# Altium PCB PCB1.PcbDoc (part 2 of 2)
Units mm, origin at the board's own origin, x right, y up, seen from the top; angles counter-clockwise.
Board outline 100 x 100 mm, 4 copper layers (Top Layer, Layer 1, Layer 2, Bottom Layer), stack 1.578 mm thick; 186 components, 85 nets, 396 pads, 143 vias.
Unrouted connection lines stored in the file: 19.
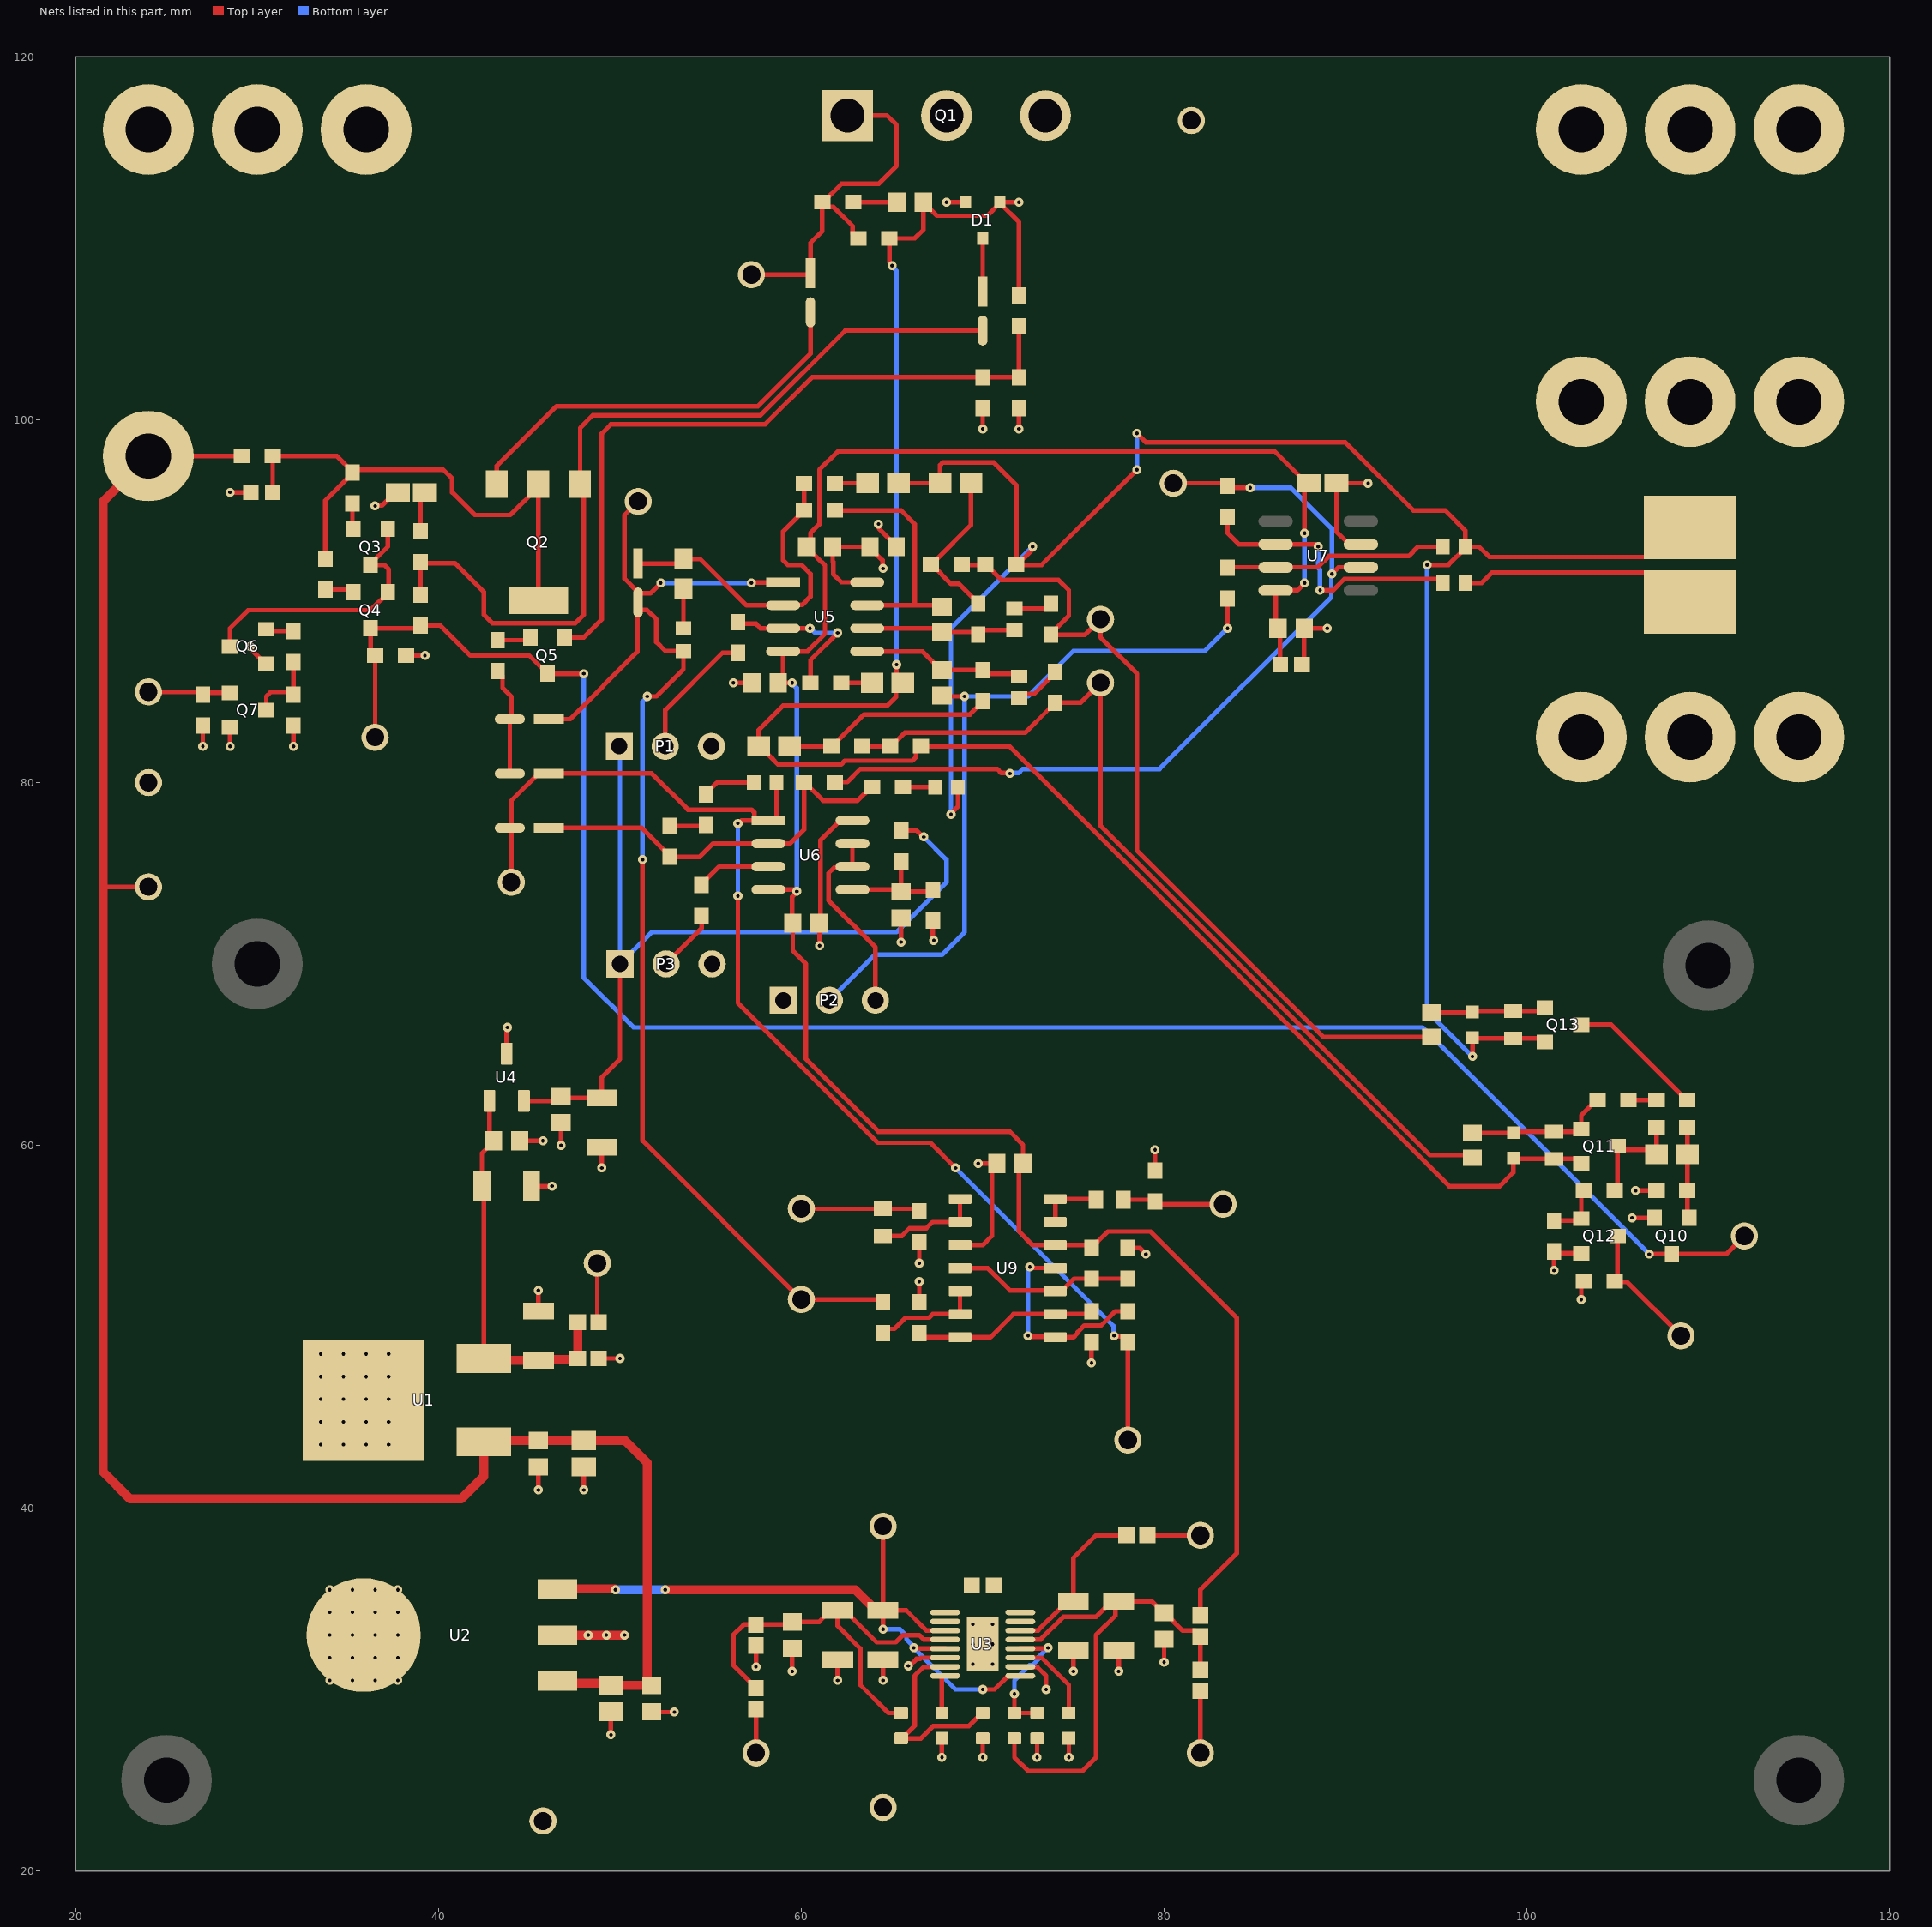
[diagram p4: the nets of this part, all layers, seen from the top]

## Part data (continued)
R48 R61: library part CMP-1012-00595-2, "Chip Resistor, 5.6 KOhm, +/- 1%, 0.1 W, -55 to 155 degC, 0603 (1608 Metric), RoHS, Tape and Reel", Case Code (Imperial)=0603, Case Code (Metric)=1608, Max Operating Temperature="155 degC", Min Operating Temperature="-55 degC", Package Quantity=5000, Power Rating="100 mW", Resistance=5.6kohm, Tolerance=1%, Type (Resistor)="Thick Film", Voltage Rating="50 V"
R49 R65: library part CMP-1012-00454-3, "RES Thick Film, 330Ω, 1%, 0.1W, 100ppm/°C, 0603", Case Code (Imperial)=0603, Case Code (Metric)=1608, Max Operating Temperature=155°C, Max Power Dissipation=100mW, Min Operating Temperature=-55°C, Package Quantity=10, Resistance=330R, Temperature Coefficient=100ppm/°C, Tolerance=1%, Voltage Rating=75V
R50 R51 R52 R63: library part CMP-03412-027829-2, "RES 47.5KΩ 1.00% 0.1W 0603", Case Code (Imperial)=0603, Case Code (Metric)=1608, Max Operating Temperature=155°C, Max Power Dissipation=100mW, Min Operating Temperature=-55°C, Ratings=AEC-Q200, Resistance=47.5kR, Resistor Type="Thick Film", Temperature Coefficient=100ppm/°C, Tolerance=1%, Voltage Rating=50V
R53 R62: library part CMP-2000-03570-1, Manufacturer="Vishay Dale"
ST1 ST2 ST3 ST4 ST5 ST6 ST7 ST8 ST9 ST10 ST11 ST12 ST13 ST14 ST15 ST16 ST17: library part CMP-00028-00004-1, "M2 PTH (2.5mm), 5mm pad"
TP1 TP2 TP3 TP4 TP5 TP6 TP7 TP8 TP9 TP10 TP11 TP12 TP13 TP14 TP15 TP16 TP17 TP18 TP19 TP20 TP21 TP22 TP23 TP24: library part CMP-002-00037-1, "Test Point, Orange, Height 4.6 mm, Tail Length 3 mm, 1-Pin THD, RoHS", Colour=Orange, Manufacturer=Keystone, Package Description="1-Pin Through Hole Device, Dia 2.54 mm", Package Quantity=10
U1: library part CMP-0244-00177-2, "IC REG LINEAR 5V 500MA DPAK", Case/Package=TO-252, Dropout Voltage=2V, Max Input Voltage=35V, Max Operating Temperature=125°C, Max Output Current=500mA, Min Input Voltage=10V, Min Operating Temperature=-40°C, Min Output Voltage=5V, Output Voltage Accuracy=2%, Package Quantity=1, Power Supply Rejection Ratio (PSRR)=62dB, Quiescent Current=6mA, Tolerance=4%
U2: library part CMP-04917-000197-1, "IC REG LINEAR 12V 1.5A", Case/Package=TO-263, Dropout Voltage=2V, Max Operating Temperature=125°C, Min Operating Temperature=0°C, Quiescent Current=8mA
U3: library part CMP-0475-00263-1, "Low Noise Dual Supply Inverting Charge Pump, 4.5 to 32 V Vin, Adjustable Vout, 16-pin SOP (MSE-16-EDP), -50 to 150 degC, Pb-Free", Frequency(kHz)=500, Manufacturer="Linear Technology"
U4: library part CMP-0367-00203-2, "20 ppm / degC Max, 100 uA Series Voltage Reference, -40 to 125 degC, 3-pin SOT-23 (DBZ), Green (RoHS & no Sb/Br)", Manufacturer="Texas Instruments", Rating=Catalog, Temp Coeff(Max)(ppm/ degree C)=20, Temp Coeff(Typ)(ppm/ degree C)=10
U5 U6: library part CMP-12131-000015-1, "IC OPAMP JFET 2 CIRCUIT 8SO", Case/Package=SO, Dual Supply Voltage=15V, Input Bias Current=200pA, Input Offset Voltage (Vos)=10mV, Input Offset Voltage-Max=3mV, Max Dual Supply Voltage=18V, Max Operating Temperature=70°C, Max Supply Voltage=36V, Min Dual Supply Voltage=3V, Min Input Voltage=-12V, Min Operating Temperature=0°C, Nominal Supply Current=2.5mA, Operating Supply Current=1.4mA, Output Current=40mA, Package Quantity=100, Voltage Gain=106.02dB
U7: library part CMP-0359-03372-2, "Single Channel, Zero-Drift Operational Amplifier, 3 MHz Typical GBW, 2 V/us Typical SR, 2.7 to 11 V, 8-Pin SOIC (S8-8), Commercial, Pb-Free", Linear Technology Part Number=LTC2050HV, Manufacturer="Linear Technology"
U9: library part CMP-0055-00405-3, "Ultra-Low Power Quad Comparator, 14-pin Narrow SOIC", Manufacturer="Texas Instruments", Package Reference=D0014A, PackageTopMarking=NSUZXYTTE#*LP339M, PowerWise=N

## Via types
v1: diameter 0.5, hole 0.2, Top Layer to Bottom Layer, 143 vias

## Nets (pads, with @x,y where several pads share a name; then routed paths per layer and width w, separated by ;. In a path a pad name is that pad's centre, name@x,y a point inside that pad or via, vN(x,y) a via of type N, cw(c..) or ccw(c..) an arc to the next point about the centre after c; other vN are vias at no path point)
0.05V: P2.2 R18.2 R37.1 | length 41
  Top Layer w0.254: R18.2@67.75,84.8 67.8,84.75 v1(69,84.75) ; v1(83.5,88.5) R37.1@83.5,90.15
  Bottom Layer w0.254: P2.2@61.54,68 64.04,70.5 67.75,70.5 69,71.75 v1(69,84.75) 72.5,84.75 75,87.25 82.25,87.25 v1(83.5,88.5)
5V: C2.1 C16.1 C18.2 FB1.1 FB5.1 U1.3 U4.1 | length 21.7
  Top Layer w0.254: U1.3@42.5,48.25 42.5,57.637 C16.1@42.387,57.75 42.387,59.562 43.025,60.2 C18.2@43.025,60.25 42.8,60.475 U4.1@42.8,62.45
  Top Layer w0.5: U1.3@42.586,48.138 C2.1@45.5,48.138 45.556,48.194 47.618,48.194 FB1.1@47.674,48.25 FB5.1@47.674,50.25
+5: C23.2 C31.2 C34.2 C35.2 C36.1 C37.2 C41.2 FB1.2 FB3.2 Q6.1 R47.2 R50.2 R56.1 R58.2 U5.8 U6.8 U7.7 U9.3 | length 39.9
  Top Layer w0.254: v1(29.6,87.5) 29.628,87.472 29.628,87.372 30.45,86.55 Q6.1@30.5,86.55 ; FB1.2@48.826,48.25 v1(50,48.25) ; v1(57.5,31.25) FB3.2@57.5,32.424 ; v1(61,71) 61,72.225 C31.2@60.975,72.25 61.046,72.321 61.046,76.816 62.135,77.905 U6.8@62.816,77.905 ; U5.8@63.632,91.04 62.21,91.04 61.754,91.496 61.754,92.163 61.725,92.192 C23.2@61.725,93 C41.2@63.775,93 63.775,92.95 64.472,92.253 64.472,91.828 v1(64.5,91.8) ; R50.2@66.5,51.35 v1(66.5,52.5) ; v1(66.5,53.5) R47.2@66.5,54.65 ; U9.3@68.75,54.5 70,54.5 70.5,55 70.5,58.725 C37.2@70.775,59 v1(69.75,59) ; R58.2@79.5,58.6 v1(79.5,59.75) ; C36.1@87.602,86.5 87.725,86.623 C34.2@87.725,88.5 v1(89,88.5) ; U7.7@90.85,93.135 90.2,93.135 89.5,93.835 C35.2@89.5,96.5 v1(91.25,96.5) ; v1(103,51.5) 103,52.35 R56.1@103.15,52.5
+REF2V5: C15.2 C17.1 P1.1 P3.1 R35.2 U4.2 | length 48.6
  Top Layer w0.254: U4.2@44.7,62.45 46.5,62.45 C15.2@46.75,62.7 46.838,62.612 C17.1@49,62.612 49,63.75 50,64.75 P3.1@50,70 ; P1.1@49.96,82 P1.1@50,81.96 ; R35.2@65.5,77.35 66.36,77.35 66.71,77 v1(66.75,77)
  Bottom Layer w0.254: P1.1@49.96,82 50,81.96 P3.1@50,70 51.75,71.75 65.25,71.75 68,74.5 68,75.75 v1(66.75,77)
-5: C23.1 C31.1 C34.1 C35.1 C36.2 C37.1 C42.1 FB4.2 R64.2 U5.4 U6.4 U7.4 U9.12 | length 128.5
  Top Layer w0.254: U6.4@58.184,74.095 59.615,74.095 59.71,74 v1(59.75,74) 59.75,73.96 59.5,73.71 59.5,72.275 C31.1@59.525,72.25 59.525,70.725 60.25,70 60.25,64.75 64.25,60.75 71.5,60.75 72.225,60.025 C37.1@72.225,59 72,58.775 72,55.25 72.75,54.5 U9.12@74,54.5 75.85,54.5 R64.2@76,54.35 76,54.4 76.273,54.673 76.323,54.673 76.9,55.25 79.25,55.25 84,50.5 84,37.5 82,35.5 FB4.2@82,34.076 ; v1(59.5,85.5) C42.1@58.725,85.5 59,85.775 U5.4@59,87.23 60.338,87.23 61.3,88.192 61.3,91.975 61.127,92.148 61.115,92.148 60.923,92.34 60.923,92.352 60.673,92.602 60.623,92.602 60.275,92.95 C23.1@60.275,93 60.507,93.232 60.507,93.757 61,94.25 61,97.25 62,98.25 86.109,98.25 87.859,96.5 C35.1@88.019,96.5 87.75,96.231 v1(87.75,93.75) ; C36.2@86.398,86.5 86.398,88.377 C34.1@86.275,88.5 86.15,88.625 U7.4@86.15,90.595 87.345,90.595 v1(87.75,91)
  Bottom Layer w0.254: v1(59.5,85.5) 59.5,85.46 59.75,85.21 v1(59.75,74) ; v1(87.75,91) v1(87.75,93.75)
GND: C1.1 C2.2 C3.2 C4.2 C5.2 C6.1 C7.1 C8.2 C9.2 C11.1 C12.1 C13.2 C14.1 C15.1 C16.2 C17.2 C18.1 C20.2 C22.1 C30.1 C41.1 C42.2 D1.2 P1.3 P2.1 P3.3 Q7.2 Q10.2 Q12.2 R2.1 R3.2 R8.1 R9.1 R17.1 R31.2 R33.2 R36.2 R43.2 R51.1 R54.1 R59.1 R63.1 R.2 ST11.1 ST12.1 ST13.1 TP2.1 TP7.1 TP13.1 U1.4 U2.2 U2.4 U3.2 U3.14 U3.17 U4.3 | length 69.1
  Top Layer w0.254: v1(27,82) R33.2@27,83.15 ; v1(28.5,82) Q7.2@28.5,83.05 ; v1(28.5,96) C20.2@29.648,96 ; v1(32,82) R31.2@32,83.15 ; v1(36.5,95.25) 36.528,95.278 36.878,95.278 37.6,96 C22.1@37.759,96 ; R17.1@38.2,87 v1(39.25,87) ; U4.3@43.75,65.05 43.75,66.41 43.8,66.46 v1(43.8,66.5) ; C18.1@44.475,60.25 v1(45.75,60.25) ; C16.2@45.112,57.75 v1(46.25,57.75) ; v1(45.5,41) C1.1@45.5,42.275 ; C2.2@45.5,50.862 v1(45.5,52) ; v1(46.75,60) C15.1@46.75,61.25 ; v1(48,41) C3.2@48,42.274 ; v1(49,58.75) C17.2@49,59.888 ; v1(49.5,27.5) C8.2@49.5,28.774 ; C7.1@51.75,28.775 51.775,28.75 v1(53,28.75) ; v1(56.25,85.5) C42.2@57.275,85.5 ; v1(59.5,31) C6.1@59.5,32.275 ; v1(62,30.5) C5.2@62,31.638 ; v1(64.25,94.25) 64.278,94.222 64.278,93.997 65.225,93.05 C41.1@65.225,93 ; v1(64.5,30.5) C9.2@64.5,31.638 ; v1(65.5,71.2) C30.1@65.5,72.525 ; v1(65.9,31.3) 65.967,31.3 66.355,31.688 66.546,31.688 66.608,31.75 U3.14@67.925,31.75 ; R36.2@67.25,72.4 67.25,71.39 67.3,71.34 v1(67.3,71.3) ; v1(67.75,26.25) C12.1@67.75,27.3 ; v1(68,112) D1.2@69.05,112 ; v1(70,26.25) R2.1@70,27.3 ; v1(70,99.5) R8.1@70,100.65 ; v1(72,99.5) R9.1@72,100.65 ; U3.2@72.075,31.25 72.084,31.241 73.009,31.241 73.5,30.75 v1(73.5,30) ; v1(73,26.25) R3.2@73,27.3 ; v1(74.75,26.25) C11.1@74.75,27.3 ; v1(75,31) C4.2@75,32.138 ; v1(76,48) R54.1@76,49.15 ; v1(77.5,31) C13.2@77.5,32.138 ; R59.1@78,54.35 78.65,54.35 v1(79,54) ; v1(80,31.5) C14.1@80,32.775 ; R43.2@96.615,91 97.5,91 98.068,91.568 107.377,91.568 R.2@109,89.945 R.2@108.2,89.945 ; v1(101.5,53.1) R63.1@101.5,54.15 101.6,54.05 Q12.2@103,54.05 ; v1(105.8,56) Q10.2@107.05,56 ; v1(106,57.5) R51.1@107.15,57.5
  Top Layer w0.5: U2.2@46.545,33 v1(50.25,33)
  other v1: 34,30.5 35.25,30.5 36.5,30.5 37.75,30.5 69.45,31.4 70.55,31.4 34,31.75 35.25,31.75 36.5,31.75 37.75,31.75 69.45,32.5 70.55,32.5 34,33 35.25,33 36.5,33 37.75,33 48.25,33 49.25,33 69.45,33.6 70.55,33.6 34,34.25 35.25,34.25 36.5,34.25 37.75,34.25 34,35.5 35.25,35.5 36.5,35.5 37.75,35.5 33.5,43.5 34.75,43.5 36,43.5 37.25,43.5 33.5,44.75 34.75,44.75 36,44.75 37.25,44.75 33.5,46 34.75,46 36,46 37.25,46 33.5,47.25 34.75,47.25 36,47.25 37.25,47.25 33.5,48.5 34.75,48.5 36,48.5 37.25,48.5
ISET: P3.2 R39.2 | length 3.5
  Top Layer w0.254: P3.2@52.54,70 54.5,71.96 R39.2@54.5,72.65
NetC1_2: C1.2 C3.1 C7.2 C8.1 R10.1 ST10.1 TP1.1 U1.1 U2.1 | length 115.6
  Top Layer w0.254: 21.5,74.25 TP1.1@24,74.25 ; ST10.1@24,98 R10.1@29.15,98
  Top Layer w0.5: ST10.1@24,98 21.5,95.5 21.5,74.25 21.5,42 23,40.5 41.25,40.5 42.5,41.75 U1.1@42.5,43.65 42.575,43.725 C1.2@45.5,43.725 C3.1@48,43.725 ; U2.1@46.545,30.46 46.662,30.343 49.383,30.343 C8.1@49.5,30.226 ; C3.1@48,43.726 50.274,43.726 51.5,42.5 C7.2@51.5,30.45 ; C8.1@49.5,30.226 C7.2@51.75,30.225
NetC4_1: C4.1 FB6.1 U3.6 | length 9.5
  Top Layer w0.254: U3.6@72.075,33.25 72.084,33.259 73.059,33.259 74.277,34.477 74.277,34.527 74.612,34.863 C4.1@75,34.863 75,37.25 76.25,38.5 FB6.1@77.924,38.5
NetC5_1: C5.1 C6.2 FB3.1 FB7.1 R1.2 U3.12 | length 24.2
  Top Layer w0.254: FB7.1@57.5,30.076 57.5,30.1 56.25,31.35 56.25,33 56.826,33.576 FB3.1@57.5,33.576 59.351,33.576 C6.2@59.5,33.725 60.975,33.725 61.613,34.362 C5.1@62,34.362 ; R1.2@65.5,28.7 64.8,28.7 63.25,30.25 63.25,32.25 62,33.5 C5.1@62,34.362 ; U3.12@67.925,32.75 66.75,32.75 66.5,33 65.6,33 65.2,32.6 64.15,32.6 62.388,34.362 C5.1@62,34.362
NetC9_1: C9.1 TP6.1 U2.3 U3.1 U3.11 U3.13 | length 39.2
  Top Layer w0.254: C9.1@64.306,34.362 C9.1@64.5,34.362 ; v1(64.5,33.327) C9.1@64.5,34.362 ; TP6.1@64.5,39 C9.1@64.5,34.362 ; v1(66.2,32.3) 66.241,32.259 67.916,32.259 U3.13@67.925,32.25 ; U3.11@67.925,33.25 67.916,33.259 66.883,33.259 65.78,34.362 C9.1@64.5,34.362 ; v1(70,30) 70.65,30 71.385,30.735 72.06,30.735 U3.1@72.075,30.75
  Top Layer w0.5: U2.3@46.545,35.54 49.71,35.54 v1(49.75,35.5) ; v1(52.5,35.5) 62.975,35.5 64.113,34.362 C9.1@64.306,34.362
  Bottom Layer w0.254: v1(64.5,33.327) 65.423,33.327 65.794,32.956 65.794,32.773 66.2,32.367 v1(66.2,32.3) 68.5,30 v1(70,30)
  Bottom Layer w0.5: v1(49.75,35.5) v1(52.5,35.5)
NetC10_1: C10.1 U3.9 U3.10
NetC10_2: C10.2 U3.7 U3.8
NetC11_2: C11.2 U3.3 | length 4.8
  Top Layer w0.254: U3.3@72.075,31.75 73.25,31.75 74.75,30.25 C11.2@74.75,28.7
NetC12_2: C12.2 U3.16 | length 2.2
  Top Layer w0.254: C12.2@67.75,28.7 67.75,30.729 67.771,30.75 U3.16@67.925,30.75
NetC13_1: C13.1 C14.2 FB4.1 FB8.1 R4.1 U3.5 | length 28.8
  Top Layer w0.254: R4.1@71.75,27.3 71.75,26.25 72.5,25.5 75.5,25.5 76.25,26.25 76.25,33 77.317,34.067 77.317,34.679 C13.1@77.5,34.863 ; U3.5@72.075,32.75 72.084,32.759 73.201,32.759 74.442,34 76.25,34 77.113,34.863 C13.1@77.5,34.863 ; FB8.1@82,31.076 FB4.1@82,32.924 82,32.948 81.698,33.25 81.025,33.25 80.05,34.225 C14.2@80,34.225 79.95,34.225 79.313,34.863 C13.1@77.5,34.863
NetC19_1: C19.1 R5.2 | length 2.4
  Top Layer w0.254: R5.2@62.85,112 C19.1@65.275,112
NetC20_1: C20.1 Q2.2 R10.2 R11.2 R12.2 | length 31.2
  Top Layer w0.254: C20.1@30.852,96 30.85,96.002 R10.2@30.85,98 34.4,98 35.25,97.15 R11.2@35.25,97.1 ; R12.2@33.75,92.35 33.75,95.55 35.25,97.05 R11.2@35.25,97.1 ; Q2.2@45.5,90.05 Q2.2@45.5,96.3 ; Q2.2@45.5,96.6 Q2.2@45.5,96.45 Q2.2@45.5,96.3 ; R11.2@35.25,97.1 35.4,97.25 40.25,97.25 40.75,96.75 40.75,96 42,94.75 43.95,94.75 Q2.2@45.5,96.3
NetC21_1: C21.1 R13.1 | length 1.7
  Top Layer w0.254: R13.1@62.2,85.5 C21.1@63.9,85.5
NetC22_2: C22.2 R15.1 | length 2.2
  Top Layer w0.254: R15.1@39,93.85 39,95.759 C22.2@39.241,96
NetC24_1: C24.1 R18.1 R21.1 U5.5 | length 8.9
  Top Layer w0.254: U5.5@63.632,87.23 66.67,87.23 67.7,86.2 R18.1@67.75,86.2 R21.1@70,86.2 70.2,86 71.85,86 C24.1@72,85.85
NetC24_2: C24.2 R16.1 | length 2.6
  Top Layer w0.254: C24.2@72,84.65 72.231,84.881 72.831,84.881 74,86.05 R16.1@74,86.1
NetC25_1: C25.1 R21.2 R22.1 | length 11.7
  Top Layer w0.254: C25.1@59.35,82 R22.1@61.65,82 61.7,82 63.45,83.75 69.3,83.75 70,84.45 R21.2@70,84.5
NetC26_1: C26.1 R29.2 | length 2.2
  Top Layer w0.254: R29.2@53.5,88.5 C26.1@53.5,90.673
NetC26_2: C26.2 D5.1 R24.1 R34.2 U5.2 | length 18.7
  Top Layer w0.254: D5.1@51,92.075 53.248,92.075 C26.2@53.5,92.327 54.423,92.327 56.98,89.77 U5.2@59,89.77 59.027,89.797 60.047,89.797 60.5,90.25 60.5,91.5 60,92 59.25,92 59,92.25 59,93.85 59.827,94.677 59.827,94.727 60.1,95 R24.1@60.15,95 R34.2@60.15,96.5
NetC27_1: C27.1 R26.2 R27.1 | length 8.9
  Top Layer w0.254: R27.1@67.15,92 R27.1@67.2,92 ; C27.1@69.35,96.5 69.35,94.2 67.473,92.323 67.473,92.273 R27.1@67.2,92 ; R26.2@69.75,89.85 69.75,89.9 68.7,90.95 68.25,90.95 R27.1@67.2,92
NetC28_1: C28.1 R26.1 R30.2 U5.6 | length 8.2
  Top Layer w0.254: U5.6@63.632,88.5 67.55,88.5 R30.2@67.75,88.3 69.6,88.3 69.7,88.4 C28.1@71.75,88.4
NetC28_2: C28.2 R32.1 | length 2.1
  Top Layer w0.254: C28.2@71.75,89.6 73.5,89.6 R32.1@73.75,89.85
NetC29_1: C29.1 R34.1 | length 1.8
  Top Layer w0.254: R34.1@61.85,96.5 C29.1@63.65,96.5
NetC30_2: C30.2 R35.1 R36.1 U6.5 | length 6.2
  Top Layer w0.254: U6.5@62.816,74.095 65.38,74.095 C30.2@65.5,73.975 ; R35.1@65.5,75.65 C30.2@65.5,73.975 ; R36.1@67.25,74.1 67.125,73.975 C30.2@65.5,73.975
NetC32_1: C32.1 D6.1 D7.2 R66.2 TP15.1 TP22.1 U6.1 | length 69.7
  Top Layer w0.254: TP15.1@44,74.5 44,77.425 D7.2@43.925,77.5 44,77.575 44,78.994 45.506,80.5 D6.1@46.075,80.5 51.75,80.5 53.75,78.5 57.257,78.5 57.406,78.351 57.406,78.034 57.535,77.905 U6.1@58.184,77.905 ; v1(56.5,73.75) 56.5,67.858 64.216,60.142 67.108,60.142 v1(68.5,58.75) ; v1(56.5,77.75) 56.54,77.75 56.695,77.905 57.503,77.905 U6.1@58.184,77.905 ; C32.1@58.627,80 58.627,78.034 58.498,77.905 U6.1@58.184,77.905 ; v1(77.25,49.5) 77.277,49.473 77.727,49.473 78,49.2 R66.2@78,49.15 TP22.1@78,43.75
  Bottom Layer w0.254: v1(56.5,73.75) v1(56.5,77.75) ; v1(68.5,58.75) 77.222,50.028 77.222,49.528 v1(77.25,49.5)
NetC32_2: C32.2 R41.2 | length 2.9
  Top Layer w0.254: R41.2@54.75,79.35 54.75,79.4 55.35,80 C32.2@57.373,80
NetC33_1: C33.1 R45.1 | length 1.8
  Top Layer w0.254: R45.1@65.6,79.75 C33.1@67.373,79.75
NetC38_1: C38.1 Q11.1 R49.1 R53.2 R55.2 | length 8.1
  Top Layer w0.254: R53.2@97,60.675 99.184,60.675 99.25,60.741 99.259,60.75 R49.1@101.5,60.75 102.85,60.75 Q11.1@103,60.9 103,61.65 103.85,62.5 R55.2@103.9,62.5
NetC39_1: C39.1 Q11.3 R52.1 R57.1 | length 6.3
  Top Layer w0.254: R57.1@104.85,57.5 105,57.65 Q11.3@105,59.95 105.2,59.75 106.9,59.75 C39.1@107.15,59.5 R52.1@107.15,61
NetC39_2: C39.2 Q10.1 R51.2 R52.2 | length 5
  Top Layer w0.254: R52.2@108.85,61 C39.2@108.85,59.5 R51.2@108.85,57.5 108.85,56.1 Q10.1@108.95,56
NetC40_2: C40.2 Q13.1 R62.1 R65.2 | length 6.4
  Top Layer w0.254: R62.1@94.75,67.325 96.934,67.325 97,67.391 97.009,67.4 R65.2@99.25,67.4 100.8,67.4 Q13.1@101,67.6
NetD1_3: D1.3 D3.1 | length 2.9
  Top Layer w0.254: D3.1@70,107.075 D1.3@70,110
NetD2_1: D2.1 Q1.1 R5.1 R7.1 TP10.1 | length 20.6
  Top Layer w0.254: TP10.1@57.25,108 60.425,108 D2.1@60.5,108.075 60.5,109.75 61.15,110.4 R5.1@61.15,112 ; Q1.1@62.54,116.772 64.728,116.772 65.245,116.255 65.245,113.995 64.261,113.011 62.211,113.011 61.2,112 R5.1@61.15,112 ; R7.1@63.15,110 63.1,110 62.827,110.273 62.827,110.673 61.765,111.735 61.415,111.735 R5.1@61.15,112
NetD2_2: D2.2 Q2.3 | length 23.1
  Top Layer w0.254: Q2.3@43.2,96.45 43.2,97.45 46.5,100.75 57.608,100.75 60.5,103.642 D2.2@60.5,105.925
NetD3_2: D3.2 Q2.1 R14.2 R15.2 | length 47.9
  Top Layer w0.254: R14.2@39,90.35 R15.2@39,92.1 ; R15.2@39,92.15 R15.2@39,92.1 ; D3.2@70,104.925 62.425,104.925 57.75,100.25 48.5,100.25 47.8,99.55 Q2.1@47.8,96.45 48,96.25 48,89.25 47.527,88.777 42.973,88.777 42.5,89.25 42.5,90.5 40.9,92.1 R15.2@39,92.1
NetD4_1: D4.1 D5.2 R29.1 R46.2 TP12.1 TP17.1 U5.1 | length 73
  Top Layer w0.254: D4.1@46.075,83.5 47.25,83.5 50.95,87.2 D5.2@50.95,89.482 ; D5.2@51,89.482 D5.2@51,89.631 ; TP12.1@51,95.5 50.25,94.75 50.25,91.244 51,90.494 D5.2@51,90.307 ; v1(51.25,75.75) 51.25,60.25 TP17.1@60,51.5 64.35,51.5 R46.2@64.5,51.35 ; v1(51.5,84.75) 52,84.75 53.5,86.25 R29.1@53.5,87.246 ; v1(52.25,91) 51.678,90.428 51.121,90.428 D5.2@51,90.307 ; R29.1@53.45,87.246 52.504,87.246 52,87.75 52,89 51.49,89.51 51.121,89.51 D5.2@51,89.631 ; v1(57.25,91) 57.27,91.02 58.98,91.02 U5.1@59,91.04 ; D5.2@51,89.631 D5.2@51,89.925 D5.2@51,90.307
  Bottom Layer w0.254: v1(51.25,75.75) 51.25,84.46 51.5,84.71 v1(51.5,84.75) ; v1(52.25,91) v1(57.25,91)
NetD4_2: D4.2 D6.2 R20.1 | length 6
  Top Layer w0.254: R20.1@43.25,86.15 43.523,85.877 43.523,85.227 44,84.75 44,83.575 D4.2@43.925,83.5 D6.2@43.925,80.5
NetD7_1: D7.1 R38.2 R42.2 R45.2 U6.2 | length 22.5
  Top Layer w0.254: D7.1@46.075,77.5 51.2,77.5 52.75,75.95 R42.2@52.75,75.9 54.4,75.9 55.135,76.635 59.385,76.635 60.15,77.4 R38.2@60.15,80 60.2,80 61.2,79 63.1,79 63.85,79.75 R45.2@63.9,79.75
NetFB5_2: FB5.2 TP3.1 | length 3.3
  Top Layer w0.254: TP3.1@48.75,53.5 48.75,50.326 FB5.2@48.826,50.25
NetFB6_2: FB6.2 TP4.1 | length 2.9
  Top Layer w0.254: FB6.2@79.076,38.5 TP4.1@82,38.5
NetFB7_2: FB7.2 TP5.1 | length 2.4
  Top Layer w0.254: TP5.1@57.5,26.5 FB7.2@57.5,28.924
NetFB8_2: FB8.2 TP8.1 | length 3.4
  Top Layer w0.254: TP8.1@82,26.5 FB8.2@82,29.924
NetP2_3: P2.3 U6.6 U6.7 | length 10.8
  Top Layer w0.254: U6.7@62.816,76.635 U6.6@62.816,75.365 62.767,75.316 61.816,75.316 61.5,75 61.5,73.5 64.08,70.92 P2.3@64.08,68
NetQ1_2: Q1.2 ST4.1 ST5.1 ST6.1
NetQ3_1: Q3.1 Q3.3 Q4.1 Q6.3 | length 15.3
  Top Layer w0.254: Q6.3@28.5,87.5 28.5,88.5 29.5,89.5 36.25,89.5 37.25,90.5 37.25,91.75 37,92 Q3.3@36.25,92 36.25,92.05 37.2,93 Q3.1@37.2,94
NetQ3_2: Q3.2 R11.1 | length 1.4
  Top Layer w0.254: R11.1@35.25,95.4 35.25,94.05 Q3.2@35.3,94
NetQ4_2: Q4.2 R12.1 | length 1.6
  Top Layer w0.254: R12.1@33.75,90.65 35.15,90.65 Q4.2@35.3,90.5
NetQ4_3: Q4.3 Q5.3 Q10.3 R14.1 R17.2 TP11.1 TP18.1 | length 106.5
  Top Layer w0.254: TP11.1@36.5,82.5 R17.2@36.5,87 36.25,87.25 Q4.3@36.25,88.5 38.85,88.5 R14.1@39,88.65 40.1,88.65 41.75,87 45,87 45.677,86.323 45.727,86.323 46,86.05 Q5.3@46,86 v1(48,86) ; v1(106.75,54) Q10.3@108,54 111,54 TP18.1@112,55
  Bottom Layer w0.254: v1(48,86) 48,69.25 50.75,66.5 94.25,66.5 v1(106.75,54)
NetQ5_1: Q5.1 R6.1 R8.2 R9.2 | length 39.8
  Top Layer w0.254: Q5.1@46.95,88 48,88 49,89 49,99.25 49.5,99.75 58,99.75 60.6,102.35 R8.2@70,102.35 R9.2@72,102.35 R6.1@72,105.15
NetQ5_2: Q5.2 R20.2 | length 1.9
  Top Layer w0.254: R20.2@43.25,87.85 44.9,87.85 Q5.2@45.05,88
NetQ6_2: Q6.2 R25.2 | length 1.5
  Top Layer w0.254: Q6.2@30.5,88.45 30.6,88.35 R25.2@32,88.35
NetQ7_1: Q7.1 R33.1 TP14.1 | length 4.8
  Top Layer w0.254: TP14.1@24,85 26.85,85 R33.1@26.925,84.925 ; Q7.1@28.5,84.95 26.95,84.95 R33.1@26.925,84.925 ; R33.1@26.925,84.925 R33.1@27,84.85 R33.1@26.925,84.925
NetQ7_3: Q7.3 R25.1 R31.1 | length 4.2
  Top Layer w0.254: Q7.3@30.5,84 30.5,84.75 30.75,85 31.85,85 R31.1@32,84.85 R25.1@32,86.65
NetQ12_1: Q12.1 R57.2 R63.2 | length 3.2
  Top Layer w0.254: R63.2@101.5,55.85 102.9,55.85 Q12.1@103,55.95 103,57.35 R57.2@103.15,57.5
NetQ12_3: Q12.3 R56.2 TP20.1 | length 7.5
  Top Layer w0.254: Q12.3@105,55 105,52.65 R56.2@104.85,52.5 104.882,52.468 105.532,52.468 TP20.1@108.5,49.5
NetQ13_3: Q13.3 R60.1 | length 7.6
  Top Layer w0.254: Q13.3@103,66.65 104.65,66.65 108.8,62.5 R60.1@108.85,62.5
NetR1_1: R1.1 R2.2 U3.15 | length 10.7
  Top Layer w0.254: R1.1@65.5,27.3 R1.1@65.55,27.3 ; U3.15@67.925,31.25 66.75,31.25 66.25,30.75 66.25,28 R1.1@65.55,27.3 ; R2.2@70,28.7 69.95,28.7 69.227,27.977 67.265,27.977 66.588,27.3 R1.1@65.55,27.3
NetR3_1: R3.1 R4.2 U3.4 | length 7.2
  Top Layer w0.254: v1(71.75,29.75) R4.2@71.75,28.7 R3.1@73,28.7 ; U3.4@72.075,32.25 72.084,32.259 73.559,32.259 v1(73.6,32.3)
  Bottom Layer w0.254: v1(71.75,29.75) 71.75,30.5 72.586,31.336 72.736,31.336 73.114,31.714 73.114,31.814 v1(73.6,32.3)
NetR13_2: R13.2 R19.1 U5.3 | length 9.1
  Top Layer w0.254: R19.1@56.5,88.85 56.6,88.75 57.5,88.75 57.75,88.5 U5.3@59,88.5 v1(60.473,88.5) ; R13.2@60.5,85.5 60.5,86.75 v1(62,88.25)
  Bottom Layer w0.254: v1(60.473,88.5) 60.513,88.5 60.763,88.25 v1(62,88.25)
NetR24_2: R24.2 R30.1 U5.7 | length 13.3
  Top Layer w0.254: R24.2@61.85,95 65.5,95 66.25,94.25 66.25,89.77 ; U5.7@63.632,89.77 66.25,89.77 ; R30.1@67.75,89.7 67.68,89.77 66.25,89.77
NetR37_2: R37.2 R40.1 U7.3 | length 12.4
  Top Layer w0.254: R37.2@83.5,91.85 83.515,91.865 U7.3@86.15,91.865 88.465,91.865 89.092,92.492 93.492,92.492 94,93 R40.1@95.385,93
NetR38_1: R38.1 R44.1 TP16.1 U7.6 | length 47.1
  Top Layer w0.254: R38.1@61.85,80 61.882,80.032 62.532,80.032 63.25,80.75 70.794,80.75 71.014,80.53 71.474,80.53 v1(71.502,80.502) ; TP16.1@80.5,96.5 83.35,96.5 R44.1@83.5,96.35 83.6,96.25 v1(84.75,96.25) ; v1(89.25,91.5) 89.615,91.865 U7.6@90.85,91.865
  Bottom Layer w0.254: v1(71.502,80.502) 71.53,80.53 71.991,80.53 72.21,80.75 79.75,80.75 89.222,90.222 89.222,91.472 v1(89.25,91.5) 89.25,94 87,96.25 v1(84.75,96.25)
NetR39_1: R39.1 U6.3 | length 4.1
  Top Layer w0.254: R39.1@54.5,74.35 54.5,74.4 55.465,75.365 U6.3@58.184,75.365
NetR41_1: R41.1 R42.1 | length 2
  Top Layer w0.254: R42.1@52.75,77.6 54.7,77.6 R41.1@54.75,77.65
NetR43_1: R43.1 R44.2 U7.2 | length 15.7
  Top Layer w0.254: R44.2@83.5,94.65 83.5,93.75 84.115,93.135 88.325,93.135 88.46,93 v1(88.5,93) ; v1@88.647,90.647 v1(88.6,90.6) 89.318,90.6 89.94,91.222 R43.1@95.357,91.222
  Bottom Layer w0.254: v1(88.5,93) 88.5,91.826 88.6,91.726 v1(88.6,90.6)
NetR46_1: R46.1 U9.5 U9.6 | length 6
  Top Layer w0.254: R46.1@64.5,49.65 64.732,49.882 65.132,49.882 65.75,50.5 67.05,50.5 67.24,50.69 U9.6@68.75,50.69 U9.5@68.75,51.96
NetR47_1: R47.1 R48.1 TP19.1 | length 6.6
  Top Layer w0.254: TP19.1@60,56.5 R48.1@64.5,56.5 66.35,56.5 R47.1@66.5,56.35
NetR48_2: R48.2 U9.1 U9.2 | length 5.8
  Top Layer w0.254: R48.2@64.5,55 65.538,55 65.965,55.427 66.889,55.427 67.232,55.77 U9.2@68.75,55.77 U9.1@68.75,57.04
NetR50_1: R50.1 R54.2 U9.7 U9.9 | length 10.2
  Top Layer w0.254: R50.1@66.5,49.65 66.73,49.42 U9.7@68.75,49.42 70.42,49.42 71.69,50.69 U9.9@74,50.69 75.84,50.69 R54.2@76,50.85
NetR55_1: R55.1 R60.2 | length 1.6
  Top Layer w0.254: R55.1@105.6,62.5 R60.2@107.15,62.5
NetR58_1: R58.1 R61.1 TP21.1 | length 5.6
  Top Layer w0.254: R61.1@77.75,57 79.4,57 R58.1@79.5,56.9 79.65,56.75 TP21.1@83.25,56.75
NetR59_2: R59.2 R64.1 U9.4 U9.10 | length 10.1
  Top Layer w0.254: U9.4@68.75,53.23 70.27,53.23 71.5,52 73.96,52 U9.10@74,51.96 74.35,51.96 75.04,52.65 R64.1@76,52.65 R59.2@78,52.65
NetR61_2: R61.2 U9.13 U9.14 | length 3.5
  Top Layer w0.254: U9.13@74,55.77 U9.14@74,57.04 76.21,57.04 R61.2@76.25,57
NetR66_1: R66.1 U9.8 U9.11 | length 11.4
  Top Layer w0.254: v1(72.5,49.5) 72.54,49.5 72.6,49.44 73.98,49.44 U9.8@74,49.42 75.006,49.42 75.235,49.649 75.235,49.698 75.611,50.073 76.535,50.073 77.312,50.85 R66.1@78,50.85 ; v1(72.6,53.3) 72.64,53.3 72.7,53.24 73.99,53.24 U9.11@74,53.23
  Bottom Layer w0.254: v1(72.5,49.5) 72.5,53.16 72.6,53.26 v1(72.6,53.3)
SENSE+: R16.2 R22.2 R23.1 R53.1 TP23.1 | length 50.6
  Top Layer w0.254: R22.2@63.35,82 R23.1@64.9,82 64.95,82 65.7,82.75 72.35,82.75 73.677,84.077 73.727,84.077 74,84.35 R16.2@74,84.4 75.4,84.4 TP23.1@76.5,85.5 76.5,77.608 94.654,59.454 96.871,59.454 R53.1@97,59.325
SENSE-: R27.2 R28.1 R32.2 R62.2 TP24.1 | length 46.5
  Top Layer w0.254: R27.2@68.85,92 R28.1@70.15,92 70.2,92 71.036,91.164 74.187,91.164 74.75,90.601 74.75,89.2 73.75,88.2 R32.2@73.75,88.15 75.65,88.15 TP24.1@76.5,89 76.5,88 78.5,86 78.5,76.25 88.775,65.975 R62.2@94.75,65.975
UOUT+: C19.2 C21.2 C25.2 C38.2 D1.1 Q1.3 Q11.2 R6.2 R7.2 R23.2 R49.2 ST1.1 ST2.1 ST3.1 TP9.1 | length 107.6
  Top Layer w0.254: v1(65,108.5) 65,108.54 64.85,108.69 R7.2@64.85,110 66.25,110 66.725,110.475 C19.2@66.725,111.95 ; v1(65.25,86.5) 65.25,85.85 C21.2@65.6,85.5 65.218,85.118 65.218,84.718 64.75,84.25 59,84.25 57.65,82.9 C25.2@57.65,82 57.725,82 58.398,81.327 58.398,81.315 58.713,81 62.194,81 62.398,81.204 66.126,81.204 66.32,81.399 66.32,81.727 66.361,81.768 66.368,81.768 R23.2@66.6,82 71.466,82 95.716,57.75 98.5,57.75 99.25,58.5 C38.2@99.25,59.3 ; C19.2@66.725,112 C19.2@66.725,111.95 ; R6.2@72,106.85 72,110.9 D1.1@70.95,111.95 ; v1(72,112) D1.1@70.95,112 D1.1@70.95,111.95 ; C38.2@99.259,59.25 R49.2@101.5,59.25 102.75,59.25 Q11.2@103,59 ; C19.2@66.725,111.95 67.073,111.602 67.123,111.602 67.475,111.25 70.25,111.25 D1.1@70.95,111.95
  Bottom Layer w0.254: v1(65,108.5) 65,108.46 65.25,108.21 v1(65.25,86.5)
UOUT-: C27.2 C29.2 C33.2 C40.1 Q13.2 R28.2 R40.2 R65.1 R.1 ST7.1 ST8.1 ST9.1 | length 113.2
  Top Layer w0.254: C29.2@65.35,96.5 C27.2@67.65,96.5 67.65,97.501 67.799,97.65 70.6,97.65 71.85,96.4 R28.2@71.85,92 R28.2@71.9,92 ; v1(68.25,78.25) 68.25,78.29 68.627,78.667 C33.2@68.627,79.75 ; v1(72.75,93) 72.722,92.972 72.722,92.822 R28.2@71.9,92 ; v1(78.5,97.25) 73.25,92 R28.2@71.9,92 ; v1(78.5,99.25) 79,98.75 90,98.75 93.75,95 95.5,95 96.615,93.885 R40.2@96.615,93 ; v1(94.5,92) 95.679,92 96.615,92.936 R40.2@96.615,93 ; v1(97,64.9) 97,65.891 97.009,65.9 R65.1@99.25,65.9 100.8,65.9 Q13.2@101,65.7 ; R.1@109,94.055 107.377,92.432 97.932,92.432 97.364,93 R40.2@96.615,93
  Bottom Layer w0.254: v1(68.25,78.25) 68.25,88.5 v1(72.75,93) ; v1(78.5,97.25) v1(78.5,99.25) ; v1(94.5,92) 94.5,67.4 v1(97,64.9)
USET: P1.2 R19.2 | length 7.3
  Top Layer w0.254: P1.2@52.5,82 52.5,84 55.65,87.15 R19.2@56.5,87.15
pads on no net: ST14.1 ST15.1 ST16.1 ST17.1 U7.1 U7.5 U7.8

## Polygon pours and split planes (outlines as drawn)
+5 on Layer 2 "NONET_L01_P-001" (solid, pour order 18): 21,102.75 96,102.75 96,77.5 118.75,77.5 118.75,21 21,21
NetQ1_2 on Layer 2 "NONET_L01_P-001" (solid, pour order 19): 21,119 60.5,119 60.5,114.75 64.5,114.75 64.5,119 70.5,119 70.5,105 21,105
UOUT+ on Layer 2 "NONET_L01_P-001" (solid, pour order 2): 71,119 71,105 119,105 119,119
GND on Top Layer "NONET_L01_P-001" (solid, pour order 17): 118.75,90.75 118.75,79 cw(c118.25,79) 118.25,78.5 99,78.5 cw(c99,79) 98.5,79 98.5,90.75 cw(c99,90.75) 99,91.25 106.5,91.25 118.25,91.25 cw(c118.25,90.75)
UOUT- on Top Layer "NONET_L01_P-001" (solid, pour order 16): 98.75,105 118.5,105 cw(c118.5,104.75) 118.75,104.75 118.75,93 cw(c118.5,93) 118.5,92.75 98.75,92.75 cw(c98.75,93) 98.5,93 98.5,104.75 cw(c98.75,104.75)
GND on Top Layer "NONET_L01_P-001" (solid, pour order 15): 42.5,39.25 21.75,39.25 ccw(c21.75,38.75) 21.25,38.75 21.25,21.5 ccw(c21.75,21.5) 21.75,21 42.5,21 ccw(c42.5,21.5) 43,21.5 43,38.75 ccw(c42.5,38.75)
GND on Top Layer "NONET_L01_P-001" (solid, pour order 14): 40,41.75 24.604,41.75 cw(c24.604,43.811) 23.146,42.354 22.927,42.573 cw(c23.957,43.604) 22.5,43.604 22.5,68.25 cw(c23,68.25) 23,68.75 40,68.75 cw(c40,68.25) 40.5,68.25 40.5,42.25 cw(c40,42.25)
NetC10_2 on Top Layer "NONET_L01_P-001" (solid, pour order 6): 70.25,36.25 70.25,35.25 71,35.25 cw(c71,35) 71.25,35 71.25,33.5 73,33.5 73,36 ccw(c72.75,36) 72.75,36.25
NetC10_1 on Top Layer "NONET_L01_P-001" (solid, pour order 5): 69.75,36.25 67.25,36.25 ccw(c67.25,36) 67,36 67,33.5 68.75,33.5 68.75,35 cw(c69,35) 69,35.25 69.75,35.25
no net on Bottom Solder "NONET_L01_P-001" (solid, pour order 11): 33,49 37.75,49 37.75,43 33,43
no net on Bottom Solder "NONET_L01_P-001" (solid, pour order 10): 33.5,36 38.25,36 38.25,30 33.5,30
no net on Bottom Solder "NONET_L01_P-001" (solid, pour order 7): 69,34.25 71,34.25 71,30.75 69,30.75
UOUT+ on Bottom Layer "NONET_L01_P-001" (solid, pour order 21): 71,119 119,119 119,105 71,105
NetQ1_2 on Bottom Layer "NONET_L01_P-001" (solid, pour order 20): 21,119 21,105 70.5,105 70.5,119 64.5,119 64.5,114.75 60.5,114.75 60.5,119
GND on Bottom Layer "NONET_L01_P-001" (solid, pour order 12): 42.5,39.25 21.75,39.25 ccw(c21.75,38.75) 21.25,38.75 21.25,21.5 ccw(c21.75,21.5) 21.75,21 42.5,21 ccw(c42.5,21.5) 43,21.5 43,38.75 ccw(c42.5,38.75)
GND on Bottom Layer "NONET_L01_P-001" (solid, pour order 13): 40,41.75 24.604,41.75 cw(c24.604,43.811) 23.146,42.354 22.927,42.573 cw(c23.957,43.604) 22.5,43.604 22.5,68.25 cw(c23,68.25) 23,68.75 40,68.75 cw(c40,68.25) 40.5,68.25 40.5,42.25 cw(c40,42.25)
GND on Layer 1 "NONET_L01_P-001" (solid, pour order 0): 21,119 119,119 119,21 21,21

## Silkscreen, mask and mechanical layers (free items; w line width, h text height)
Top Overlay:
  text "Master thesis" at 88.654,26.154 h1.52
  text "Regulator" at 88.654,24.062 h1.52
  text "Petr Sebesta" at 88.654,21.454 h1.52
